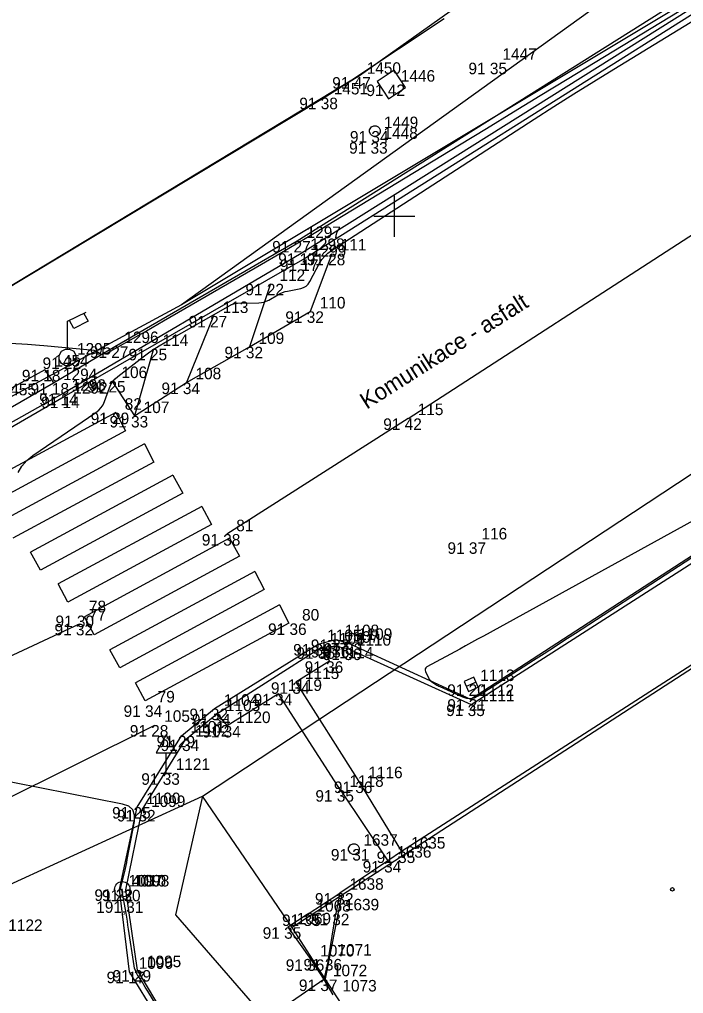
# Model space of a CAD drawing. Extents: x -711081 to -709338, y -1025122 to -1024092.
# Drawn here: x -710959.11 to -710942.97, y -1025043.88 to -1025020.22 of the extents above; entities that cross this region are included whole.
import ezdxf

# ---------------------------------------------------------------- set-up
doc = ezdxf.new("R2010")
doc.units = 0
for name, color, linetype in [('Ex_Minor Contours', 7, 'Continuous'), ('Z_bodove_pole', 7, 'Continuous'), ('Z_bodove_pole_cisla', 7, 'Continuous'), ('Z_bodove_pole_vysky', 7, 'Continuous'), ('Z_body', 7, 'Continuous'), ('Z_body_cisla', 7, 'Continuous'), ('Z_body_vysky_redukovane', 7, 'Continuous'), ('Z_budova', 7, 'Continuous'), ('Z_dopravni_znacky', 7, 'Continuous'), ('Z_hektometricka_sit', 7, 'Continuous'), ('Z_katastr_hranice', 7, 'Continuous'), ('Z_katastr_vnitrni_kresba', 7, 'Continuous'), ('Z_katastr_znacky_budov', 7, 'Continuous'), ('Z_komunikace', 7, 'Continuous'), ('Z_komunikace_osa', 7, 'Continuous'), ('Z_obruba', 7, 'Continuous'), ('Z_popisy', 7, 'Continuous'), ('Z_rozhranni', 7, 'Continuous'), ('Z_site_kanalizace_znaky', 7, 'Continuous'), ('Z_site_nerozlisene_znaky', 7, 'Continuous'), ('Z_site_vo_znaky', 7, 'Continuous'), ('Z_site_vodovod_znaky', 7, 'Continuous'), ('Z_vdz12_plna', 7, 'Continuous'), ('Z_vdz25_prerusovana', 7, 'Continuous'), ('Z_vdz50', 7, 'Continuous'), ('Z_vdz_prechod', 7, 'Continuous'), ('Z_vstupy', 7, 'Continuous')]:
    doc.layers.add(name, color=color, linetype=linetype)

# ---------------------------------------------------------------- blocks, each defined once
blk = doc.blocks.new('POINT_DISPLAY')
blk.add_line((0, 0), (0, 0))
blk = doc.blocks.new('Z614')
for p, q in [((-0.13, 0.03), (-0.1, 0.08)), ((-0.13, -0.03), (-0.13, 0.03)), ((-0.1, 0.08), (-0.08, 0.1)), ((-0.08, 0.1), (-0.03, 0.13)), ((-0.03, 0.13), (0.03, 0.13)), ((0.03, 0.13), (0.08, 0.1)), ((0.08, 0.1), (0.1, 0.08)), ((0.1, 0.08), (0.13, 0.03)), ((0.13, 0.03), (0.13, -0.03)), ((-0.1, -0.08), (-0.13, -0.03)), ((-0.08, -0.1), (-0.1, -0.08)), ((-0.03, -0.13), (-0.08, -0.1)), ((0.03, -0.13), (-0.03, -0.13)), ((0.08, -0.1), (0.03, -0.13)), ((0.1, -0.08), (0.08, -0.1)), ((0.13, -0.03), (0.1, -0.08))]:
    blk.add_line(p, q)
blk = doc.blocks.new('Z13')
for p, q in [((0, 0.88), (0.45, 1.1)), ((0.4, 1.07), (0.5, 0.88)), ((0, 0.2), (0, 0.88)), ((0.15, 0.7), (0.05, 0.9)), ((0.5, 0.88), (0.15, 0.7)), ((-0.2, 0.05), (-0.15, 0.15)), ((-0.2, -0.05), (-0.2, 0.05)), ((-0.15, 0.15), (-0.05, 0.2)), ((-0.05, 0.2), (0.05, 0.2)), ((0.05, 0.2), (0.15, 0.15)), ((0.15, 0.15), (0.2, 0.05)), ((0.2, 0.05), (0.2, -0.05)), ((-0.15, -0.15), (-0.2, -0.05)), ((-0.05, -0.2), (-0.15, -0.15)), ((0.05, -0.2), (-0.05, -0.2)), ((0.15, -0.15), (0.05, -0.2)), ((0.2, -0.05), (0.15, -0.15))]:
    blk.add_line(p, q)
blk = doc.blocks.new('Z46260')
for p, q in [((0.13, 0.13), (-0.13, 0.13)), ((-0.13, 0.13), (-0.13, -0.13)), ((0.13, 0), (-0.13, 0)), ((0.13, -0.13), (0.13, 0.13)), ((-0.13, -0.13), (0.13, -0.13))]:
    blk.add_line(p, q)
blk = doc.blocks.new('Z608')
for p, q in [((0.25, 0.25), (-0.25, 0.25)), ((-0.25, 0.25), (-0.25, -0.25)), ((0.25, -0.25), (0.25, 0.25)), ((-0.25, -0.25), (0.25, -0.25))]:
    blk.add_line(p, q)
blk = doc.blocks.new('Z527')
for p, q in [((0, 0.93), (-0.25, 0.5)), ((0.25, 0.5), (0, 0.93)), ((-0.25, 0.5), (0.25, 0.5)), ((0, 0), (0, 0.5)), ((-0.13, 0), (0.13, 0))]:
    blk.add_line(p, q)
blk = doc.blocks.new('Z101')
for radius in [0.188, 0.0025]:
    blk.add_circle((0, 0), radius)

msp = doc.modelspace()

# ---------------------------------------------------------------- linework, layer by layer
at = {"layer": 'Ex_Minor Contours'}
for points in [[(-710942.171, -1025019.465), (-710945.798, -1025021.678), (-710946.452, -1025022.076), (-710947.105, -1025022.475), (-710947.759, -1025022.873), (-710948.413, -1025023.271), (-710951.466, -1025025.128), (-710951.904, -1025025.393), (-710952.343, -1025025.655), (-710952.784, -1025025.915), (-710953.226, -1025026.172), (-710955.609, -1025027.549), (-710955.747, -1025027.628), (-710955.884, -1025027.708), (-710956.022, -1025027.787), (-710956.16, -1025027.865), (-710956.957, -1025028.32), (-710956.972, -1025028.328), (-710956.988, -1025028.334), (-710957.004, -1025028.339), (-710957.02, -1025028.342), (-710957.088, -1025028.353), (-710957.104, -1025028.354), (-710957.12, -1025028.352), (-710957.135, -1025028.347), (-710957.149, -1025028.338), (-710957.218, -1025028.29), (-710957.234, -1025028.28), (-710957.252, -1025028.273), (-710957.27, -1025028.267), (-710957.289, -1025028.264), (-710958.519, -1025028.149), (-710958.618, -1025028.14), (-710958.717, -1025028.132), (-710958.816, -1025028.124), (-710958.915, -1025028.118), (-710959.33, -1025028.091)], [(-710959.142, -1025031.227), (-710959.049, -1025031.069), (-710958.929, -1025030.93), (-710958.782, -1025030.811), (-710957.25, -1025029.766), (-710957.182, -1025029.712), (-710957.125, -1025029.649), (-710957.078, -1025029.579), (-710957.042, -1025029.5), (-710956.921, -1025029.167), (-710956.885, -1025029.087), (-710956.84, -1025029.015), (-710956.785, -1025028.949), (-710956.72, -1025028.892), (-710956.103, -1025028.415), (-710955.975, -1025028.32), (-710955.844, -1025028.229), (-710955.71, -1025028.144), (-710955.572, -1025028.063), (-710953.983, -1025027.161), (-710953.969, -1025027.154), (-710953.955, -1025027.147), (-710953.941, -1025027.142), (-710953.927, -1025027.137), (-710953.867, -1025027.118), (-710953.853, -1025027.113), (-710953.838, -1025027.11), (-710953.822, -1025027.108), (-710953.807, -1025027.108), (-710953.291, -1025027.101), (-710953.228, -1025027.096), (-710953.167, -1025027.083), (-710953.109, -1025027.063), (-710953.052, -1025027.035), (-710952.83, -1025026.905), (-710952.774, -1025026.876), (-710952.715, -1025026.851), (-710952.655, -1025026.831), (-710952.593, -1025026.816), (-710952.273, -1025026.752), (-710952.203, -1025026.73), (-710952.143, -1025026.696), (-710952.093, -1025026.649), (-710952.053, -1025026.588), (-710951.814, -1025026.142), (-710951.757, -1025026.05), (-710951.691, -1025025.967), (-710951.614, -1025025.893), (-710951.527, -1025025.829), (-710946.599, -1025022.642), (-710946.119, -1025022.334), (-710945.636, -1025022.028), (-710945.152, -1025021.725), (-710944.666, -1025021.426), (-710941.831, -1025019.69)], [(-710942.168, -1025032.08), (-710947.833, -1025035.197), (-710947.977, -1025035.276), (-710948.121, -1025035.355), (-710948.266, -1025035.434), (-710948.41, -1025035.513), (-710949.205, -1025035.947), (-710949.234, -1025035.968), (-710949.25, -1025035.994), (-710949.252, -1025036.024), (-710949.241, -1025036.058), (-710949.161, -1025036.225), (-710949.148, -1025036.25), (-710949.131, -1025036.272), (-710949.111, -1025036.291), (-710949.089, -1025036.308), (-710948.993, -1025036.371), (-710948.968, -1025036.386), (-710948.944, -1025036.4), (-710948.918, -1025036.413), (-710948.893, -1025036.426), (-710948.344, -1025036.676), (-710948.245, -1025036.708), (-710948.148, -1025036.715), (-710948.053, -1025036.695), (-710947.959, -1025036.648), (-710946.615, -1025035.785), (-710946.36, -1025035.621), (-710946.105, -1025035.457), (-710945.851, -1025035.292), (-710945.597, -1025035.127), (-710940.917, -1025032.081)], [(-710955.493, -1025044.634), (-710955.99, -1025043.822), (-710956.021, -1025043.772), (-710956.052, -1025043.722), (-710956.083, -1025043.672), (-710956.114, -1025043.622), (-710956.24, -1025043.423), (-710956.269, -1025043.372), (-710956.292, -1025043.319), (-710956.309, -1025043.264), (-710956.321, -1025043.207), (-710956.456, -1025042.319), (-710956.471, -1025042.222), (-710956.486, -1025042.126), (-710956.502, -1025042.029), (-710956.519, -1025041.932), (-710956.618, -1025041.363), (-710956.62, -1025041.359), (-710956.622, -1025041.356), (-710956.625, -1025041.354), (-710956.629, -1025041.353), (-710956.648, -1025041.351), (-710956.651, -1025041.35), (-710956.654, -1025041.348), (-710956.655, -1025041.345), (-710956.654, -1025041.341), (-710956.55, -1025040.916), (-710956.533, -1025040.843), (-710956.517, -1025040.771), (-710956.502, -1025040.698), (-710956.488, -1025040.625), (-710956.316, -1025039.705), (-710956.309, -1025039.545), (-710956.355, -1025039.421), (-710956.454, -1025039.333), (-710956.605, -1025039.281), (-710959.896, -1025038.636)]]:
    msp.add_lwpolyline(points, dxfattribs=at)
at = {"layer": 'Z_budova'}
for p, q in [((-710950.9, -1025021.62), (-710951.7, -1025022.12)), ((-710951.7, -1025022.12), (-710960.53, -1025027.43)), ((-710939.85, -1025034.02), (-710949.82, -1025040.43)), ((-710949.82, -1025040.43), (-710950.16, -1025040.66)), ((-710950.16, -1025040.66), (-710951.32, -1025041.44)), ((-710951.32, -1025041.44), (-710951.42, -1025041.94)), ((-710951.6, -1025043.04), (-710951.71, -1025043.54)), ((-710951.71, -1025043.54), (-710951.49, -1025043.91))]:
    msp.add_line(p, q, dxfattribs=at)
at = {"layer": 'Z_hektometricka_sit'}
for p, q in [((-710950, -1025024.5), (-710950, -1025025.5)), ((-710950.5, -1025025), (-710949.5, -1025025))]:
    msp.add_line(p, q, dxfattribs=at)
at = {"layer": 'Z_katastr_hranice'}
for p, q in [((-710932.67, -1025010.97), (-710955.17, -1025027.15)), ((-710942.53, -1025019.56), (-710955.17, -1025027.15)), ((-710951.03, -1025021.69), (-710948.79, -1025020.2)), ((-710964.14, -1025029.59), (-710951.03, -1025021.69)), ((-710954.66, -1025039.09), (-710931.09, -1025023.55)), ((-710955.17, -1025027.15), (-710963.45, -1025031.62)), ((-710941.71, -1025035.3), (-710951.28, -1025041.5)), ((-710988.36, -1025054.5), (-710954.66, -1025039.09)), ((-710952.48, -1025042.28), (-710954.66, -1025039.09)), ((-710951.28, -1025041.5), (-710952.48, -1025042.28)), ((-710951.68, -1025043.52), (-710952.48, -1025042.28)), ((-710949.28, -1025047.22), (-710951.68, -1025043.52))]:
    msp.add_line(p, q, dxfattribs=at)
at = {"layer": 'Z_katastr_vnitrni_kresba'}
for p, q in [((-710954.66, -1025039.09), (-710955.32, -1025041.97)), ((-710951.28, -1025041.5), (-710951.68, -1025043.52)), ((-710955.32, -1025041.97), (-710948.24, -1025050.1))]:
    msp.add_line(p, q, dxfattribs=at)
at = {"layer": 'Z_katastr_znacky_budov'}
msp.add_circle((-710943.242, -1025041.35), 0.0437, dxfattribs=at)
at = {"layer": 'Z_komunikace'}
for p, q in [((-710952.26, -1025025.9), (-710941.85, -1025019.35)), ((-710958.07, -1025029.31), (-710952.26, -1025025.9)), ((-710961.03, -1025030.98), (-710958.07, -1025029.31)), ((-710948.15, -1025036.73), (-710940.54, -1025031.79)), ((-710951.85, -1025035.39), (-710951.42, -1025035.28)), ((-710951.42, -1025035.28), (-710951.11, -1025035.37)), ((-710951.11, -1025035.37), (-710948.15, -1025036.73)), ((-710954.37, -1025036.96), (-710951.85, -1025035.39)), ((-710955.17, -1025037.62), (-710954.37, -1025036.96)), ((-710956.25, -1025039.35), (-710955.17, -1025037.62)), ((-710956.68, -1025041.35), (-710956.25, -1025039.35)), ((-710956.43, -1025043.35), (-710956.68, -1025041.35)), ((-710955.58, -1025044.75), (-710956.43, -1025043.35))]:
    msp.add_line(p, q, dxfattribs=at)
at = {"layer": 'Z_komunikace_osa'}
for q in [(-710940.68, -1025024.1), (-710954.07, -1025032.72)]:
    msp.add_line((-710949.66, -1025029.91), q, dxfattribs=at)
at = {"layer": 'Z_obruba'}
for p, q in [((-710952.36, -1025025.6), (-710941.97, -1025019.06)), ((-710956.79, -1025028.16), (-710952.36, -1025025.6)), ((-710958.28, -1025029.05), (-710956.79, -1025028.16)), ((-710961.25, -1025030.75), (-710958.28, -1025029.05)), ((-710948.13, -1025036.86), (-710940.48, -1025031.96)), ((-710954.31, -1025037.09), (-710951.77, -1025035.47)), ((-710951.77, -1025035.47), (-710951.42, -1025035.44)), ((-710951.42, -1025035.44), (-710951.13, -1025035.5)), ((-710951.13, -1025035.5), (-710948.13, -1025036.86)), ((-710955.07, -1025037.71), (-710954.31, -1025037.09)), ((-710956.13, -1025039.42), (-710955.07, -1025037.71)), ((-710956.52, -1025041.36), (-710956.13, -1025039.42)), ((-710956.24, -1025043.31), (-710956.52, -1025041.36)), ((-710955.43, -1025044.66), (-710956.24, -1025043.31))]:
    msp.add_line(p, q, dxfattribs=at)
at = {"layer": 'Z_rozhranni'}
for p, q in [((-710952.22, -1025026.05), (-710941.72, -1025019.43)), ((-710958.02, -1025029.38), (-710952.22, -1025026.05)), ((-710958.49, -1025028.73), (-710959.76, -1025029.42)), ((-710958.49, -1025028.73), (-710958.28, -1025029.05)), ((-710960.92, -1025031.05), (-710958.02, -1025029.38)), ((-710951.77, -1025035.47), (-710951.57, -1025035.81)), ((-710951.57, -1025035.81), (-710952.39, -1025036.32)), ((-710952.39, -1025036.32), (-710950.86, -1025038.73)), ((-710952.81, -1025036.6), (-710954.06, -1025037.38)), ((-710951.31, -1025038.94), (-710952.81, -1025036.6)), ((-710954.31, -1025037.09), (-710954.06, -1025037.38)), ((-710950.86, -1025038.73), (-710949.82, -1025040.43)), ((-710951.31, -1025038.94), (-710950.16, -1025040.66)), ((-710952.12, -1025041.96), (-710951.32, -1025041.44)), ((-710952.12, -1025041.96), (-710952.59, -1025042.27)), ((-710952.59, -1025042.27), (-710952.03, -1025043.05)), ((-710952.03, -1025043.05), (-710951.71, -1025043.54)), ((-710951.71, -1025043.54), (-710952.94, -1025044.39))]:
    msp.add_line(p, q, dxfattribs=at)
at = {"layer": 'Z_vdz12_plna'}
for p, q in [((-710953.52, -1025028.17), (-710952.04, -1025027.31)), ((-710955.05, -1025029.04), (-710953.52, -1025028.17)), ((-710956.86, -1025029), (-710956.31, -1025029.85)), ((-710956.31, -1025029.85), (-710955.05, -1025029.04)), ((-710959.91, -1025035.95), (-710957.65, -1025034.9))]:
    msp.add_line(p, q, dxfattribs=at)
at = {"layer": 'Z_vdz25_prerusovana'}
msp.add_line((-710960.75, -1025039.81), (-710955.82, -1025037.36), dxfattribs=at)
at = {"layer": 'Z_vdz50'}
for p, q in [((-710951.52, -1025025.91), (-710952.04, -1025027.31)), ((-710953.01, -1025026.64), (-710953.52, -1025028.17)), ((-710954.39, -1025027.42), (-710955.05, -1025029.04)), ((-710955.85, -1025028.22), (-710956.31, -1025029.85))]:
    msp.add_line(p, q, dxfattribs=at)
at = {"layer": 'Z_vdz_prechod'}
for p, q in [((-710956.77, -1025029.77), (-710960.27, -1025031.66)), ((-710956.77, -1025029.77), (-710956.53, -1025030.21)), ((-710956.53, -1025030.21), (-710960.03, -1025032.1)), ((-710956.07, -1025030.53), (-710959.5, -1025032.38)), ((-710956.07, -1025030.53), (-710955.84, -1025030.97)), ((-710955.84, -1025030.97), (-710959.27, -1025032.82)), ((-710955.38, -1025031.29), (-710958.84, -1025033.16)), ((-710955.38, -1025031.29), (-710955.14, -1025031.73)), ((-710955.14, -1025031.73), (-710958.6, -1025033.6)), ((-710954.68, -1025032.05), (-710958.17, -1025033.93)), ((-710954.68, -1025032.05), (-710954.44, -1025032.49)), ((-710954.44, -1025032.49), (-710957.93, -1025034.37)), ((-710954, -1025032.82), (-710957.53, -1025034.73)), ((-710954, -1025032.82), (-710953.76, -1025033.26)), ((-710958.6, -1025033.6), (-710958.84, -1025033.16)), ((-710953.76, -1025033.26), (-710957.29, -1025035.17)), ((-710953.39, -1025033.63), (-710956.91, -1025035.53)), ((-710953.39, -1025033.63), (-710953.16, -1025034.07)), ((-710957.93, -1025034.37), (-710958.17, -1025033.93)), ((-710953.16, -1025034.07), (-710956.67, -1025035.97)), ((-710952.79, -1025034.44), (-710956.29, -1025036.33)), ((-710952.79, -1025034.44), (-710952.56, -1025034.88)), ((-710957.29, -1025035.17), (-710957.53, -1025034.73)), ((-710952.56, -1025034.88), (-710956.05, -1025036.77)), ((-710956.67, -1025035.97), (-710956.91, -1025035.53)), ((-710956.05, -1025036.77), (-710956.29, -1025036.33))]:
    msp.add_line(p, q, dxfattribs=at)
at = {"layer": 'Z_vstupy'}
for p, q in [((-710950.9, -1025021.62), (-710948.33, -1025019.8)), ((-710951.6, -1025043.04), (-710951.42, -1025041.94))]:
    msp.add_line(p, q, dxfattribs=at)

# ---------------------------------------------------------------- block references
at = {"layer": 'Z_bodove_pole'}
msp.add_blockref('Z101', (-710956.61, -1025041.35), dxfattribs=at)
at = {"layer": 'Z_body'}
for p in [(-710947.59, -1025021.27), (-710950.9, -1025021.62), (-710950.07, -1025021.8), (-710951.7, -1025022.12), (-710950.47, -1025022.93), (-710950.49, -1025023.2), (-710952.36, -1025025.6), (-710952.26, -1025025.9), (-710951.52, -1025025.91), (-710952.22, -1025026.05), (-710953.01, -1025026.64), (-710952.04, -1025027.31), (-710954.39, -1025027.42), (-710956.79, -1025028.16), (-710955.85, -1025028.22), (-710953.52, -1025028.17), (-710957.94, -1025028.43), (-710958.49, -1025028.73), (-710958.28, -1025029.05), (-710956.86, -1025029), (-710955.05, -1025029.04), (-710958.07, -1025029.31), (-710958.02, -1025029.38), (-710956.77, -1025029.77), (-710956.31, -1025029.85), (-710949.66, -1025029.91), (-710954.07, -1025032.72), (-710948.1, -1025032.92), (-710957.65, -1025034.7), (-710957.65, -1025034.9), (-710952.46, -1025034.89), (-710951.42, -1025035.28), (-710951.11, -1025035.37), (-710951.85, -1025035.39), (-710951.77, -1025035.47), (-710951.42, -1025035.44), (-710951.13, -1025035.5), (-710951.57, -1025035.81), (-710952.39, -1025036.32), (-710948.13, -1025036.37), (-710952.81, -1025036.6), (-710948.15, -1025036.73), (-710955.97, -1025036.88), (-710954.37, -1025036.96), (-710948.13, -1025036.86), (-710954.31, -1025037.09), (-710955.82, -1025037.36), (-710954.06, -1025037.38), (-710955.17, -1025037.62), (-710955.07, -1025037.71), (-710955.54, -1025038.53), (-710950.86, -1025038.73), (-710951.31, -1025038.94), (-710956.25, -1025039.35), (-710956.13, -1025039.42), (-710950.98, -1025040.37), (-710949.82, -1025040.43), (-710950.16, -1025040.66), (-710956.68, -1025041.35), (-710956.61, -1025041.35), (-710956.52, -1025041.36), (-710951.32, -1025041.44), (-710952.12, -1025041.96), (-710951.42, -1025041.94), (-710952.59, -1025042.27), (-710952.03, -1025043.05), (-710951.6, -1025043.04), (-710956.43, -1025043.35), (-710956.24, -1025043.31), (-710951.71, -1025043.54)]:
    msp.add_blockref('POINT_DISPLAY', p, dxfattribs=at)
at = {"layer": 'Z_dopravni_znacky'}
msp.add_blockref('Z527', (-710955.54, -1025038.53), dxfattribs=at)
at = {"layer": 'Z_site_kanalizace_znaky', "rotation": 23.399999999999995}
msp.add_blockref('Z46260', (-710948.13, -1025036.37), dxfattribs=at)
at = {"layer": 'Z_site_nerozlisene_znaky', "rotation": 33.3}
msp.add_blockref('Z608', (-710950.07, -1025021.8), dxfattribs=at)
at = {"layer": 'Z_site_vo_znaky'}
msp.add_blockref('Z13', (-710957.94, -1025028.43), dxfattribs=at)
at = {"layer": 'Z_site_vodovod_znaky'}
for p in [(-710950.47, -1025022.93), (-710950.98, -1025040.37)]:
    msp.add_blockref('Z614', p, dxfattribs=at)

# ---------------------------------------------------------------- texts
at = {"layer": 'Z_bodove_pole_cisla'}
msp.add_text('4010', height=0.28, dxfattribs=at).set_placement((-710956.38, -1025041.28))
at = {"layer": 'Z_bodove_pole_vysky'}
msp.add_text('191,31', height=0.28, dxfattribs=at).set_placement((-710957.243, -1025041.92))
at = {"layer": 'Z_body_cisla'}
for s, p in [('1447', (-710947.37, -1025021.2)), ('1450', (-710950.67, -1025021.54)), ('1446', (-710949.84, -1025021.73)), ('1451', (-710951.47, -1025022.04)), ('1449', (-710950.25, -1025022.86)), ('1448', (-710950.26, -1025023.12)), ('1297', (-710952.13, -1025025.53)), ('1298', (-710952.04, -1025025.82)), ('111', (-710951.3, -1025025.83)), ('1299', (-710952, -1025025.98)), ('112', (-710952.79, -1025026.57)), ('113', (-710954.17, -1025027.35)), ('110', (-710951.81, -1025027.24)), ('1296', (-710956.56, -1025028.08)), ('114', (-710955.63, -1025028.15)), ('109', (-710953.3, -1025028.1)), ('1295', (-710957.71, -1025028.36)), ('1454', (-710958.26, -1025028.65)), ('1294', (-710958.05, -1025028.98)), ('106', (-710956.63, -1025028.93)), ('108', (-710954.83, -1025028.96)), ('1293', (-710957.84, -1025029.24)), ('1455', (-710959.54, -1025029.35)), ('1292', (-710957.8, -1025029.31)), ('82', (-710956.55, -1025029.7)), ('107', (-710956.09, -1025029.78)), ('115', (-710949.43, -1025029.83)), ('81', (-710953.84, -1025032.65)), ('116', (-710947.88, -1025032.85)), ('78', (-710957.42, -1025034.62)), ('77', (-710957.42, -1025034.82)), ('80', (-710952.24, -1025034.82)), ('1105', (-710951.63, -1025035.32)), ('1106', (-710951.55, -1025035.4)), ('1108', (-710951.2, -1025035.2)), ('1107', (-710951.2, -1025035.36)), ('1110', (-710950.91, -1025035.43)), ('1109', (-710950.88, -1025035.29)), ('1114', (-710951.34, -1025035.74)), ('1115', (-710952.17, -1025036.24)), ('1113', (-710947.91, -1025036.29)), ('1119', (-710952.59, -1025036.53)), ('79', (-710955.75, -1025036.81)), ('1112', (-710947.92, -1025036.65)), ('1111', (-710947.91, -1025036.78)), ('1104', (-710954.14, -1025036.89)), ('1103', (-710954.09, -1025037.02)), ('105', (-710955.59, -1025037.28)), ('1120', (-710953.84, -1025037.31)), ('1101', (-710954.95, -1025037.54)), ('1102', (-710954.84, -1025037.64)), ('1121', (-710955.31, -1025038.45)), ('1116', (-710950.63, -1025038.65)), ('1118', (-710951.09, -1025038.86)), ('1100', (-710956.03, -1025039.28)), ('1099', (-710955.91, -1025039.35)), ('1637', (-710950.75, -1025040.29)), ('1635', (-710949.59, -1025040.36)), ('1636', (-710949.93, -1025040.58)), ('1097', (-710956.46, -1025041.28)), ('1098', (-710956.3, -1025041.28)), ('1638', (-710951.09, -1025041.36)), ('1068', (-710951.89, -1025041.89)), ('1639', (-710951.2, -1025041.86)), ('1069', (-710952.37, -1025042.2)), ('1122', (-710959.38, -1025042.36)), ('1070', (-710951.8, -1025042.98)), ('1071', (-710951.38, -1025042.96)), ('1096', (-710956.21, -1025043.28)), ('1095', (-710956.01, -1025043.24)), ('1072', (-710951.49, -1025043.46)), ('1073', (-710951.26, -1025043.83))]:
    msp.add_text(s, height=0.28, dxfattribs=at).set_placement(p)
at = {"layer": 'Z_body_vysky_redukovane'}
for s, p in [('91 35', (-710948.197, -1025021.55)), ('91 47', (-710951.507, -1025021.9)), ('91 42', (-710950.677, -1025022.08)), ('91 38', (-710952.307, -1025022.4)), ('91 34', (-710951.077, -1025023.21)), ('91 33', (-710951.097, -1025023.48)), ('91 27', (-710952.967, -1025025.88)), ('91 17', (-710952.82, -1025026.18)), ('91 28', (-710952.127, -1025026.19)), ('91 17', (-710952.78, -1025026.33)), ('91 22', (-710953.617, -1025026.92)), ('91 32', (-710952.647, -1025027.59)), ('91 27', (-710954.997, -1025027.7)), ('91 27', (-710957.397, -1025028.44)), ('91 25', (-710956.457, -1025028.5)), ('91 32', (-710954.127, -1025028.45)), ('91 22', (-710958.547, -1025028.71)), ('91 18', (-710959.05, -1025029.01)), ('91 18', (-710958.84, -1025029.33)), ('91 25', (-710957.467, -1025029.28)), ('91 34', (-710955.657, -1025029.32)), ('91 14', (-710958.63, -1025029.59)), ('91 14', (-710958.58, -1025029.66)), ('91 29', (-710957.377, -1025030.05)), ('91 33', (-710956.917, -1025030.13)), ('91 42', (-710950.267, -1025030.19)), ('91 38', (-710954.677, -1025033)), ('91 37', (-710948.707, -1025033.2)), ('91 32', (-710958.257, -1025035.18)), ('91 30', (-710958.233, -1025034.98)), ('91 36', (-710953.067, -1025035.17)), ('91 33', (-710952.027, -1025035.56)), ('91 33', (-710951.717, -1025035.65)), ('91 34', (-710952.457, -1025035.67)), ('91 36', (-710952.377, -1025035.75)), ('91 36', (-710952.027, -1025035.72)), ('91 36', (-710951.737, -1025035.78)), ('91 36', (-710952.177, -1025036.09)), ('91 34', (-710952.997, -1025036.6)), ('91 20', (-710948.713, -1025036.65)), ('91 34', (-710953.417, -1025036.88)), ('91 21', (-710948.71, -1025037.01)), ('91 34', (-710956.577, -1025037.16)), ('91 32', (-710954.977, -1025037.24)), ('91 35', (-710948.737, -1025037.14)), ('91 34', (-710954.917, -1025037.37)), ('91 28', (-710956.427, -1025037.64)), ('91 34', (-710954.667, -1025037.66)), ('91 29', (-710955.777, -1025037.9)), ('91 34', (-710955.677, -1025037.99)), ('91 33', (-710956.147, -1025038.81)), ('91 36', (-710951.467, -1025039.01)), ('91 35', (-710951.917, -1025039.22)), ('91 25', (-710956.857, -1025039.63)), ('91 32', (-710956.737, -1025039.7)), ('91 31', (-710951.54, -1025040.65)), ('91 35', (-710950.427, -1025040.71)), ('91 34', (-710950.767, -1025040.94)), ('91 22', (-710957.287, -1025041.63)), ('91 30', (-710957.103, -1025041.64)), ('91 32', (-710951.927, -1025041.72)), ('91 35', (-710952.727, -1025042.24)), ('91 32', (-710952.027, -1025042.22)), ('91 35', (-710953.197, -1025042.55)), ('91 36', (-710952.637, -1025043.33)), ('91 36', (-710952.207, -1025043.32)), ('91 17', (-710956.99, -1025043.63)), ('91 29', (-710956.847, -1025043.59)), ('91 37', (-710952.317, -1025043.82))]:
    msp.add_text(s, height=0.28, dxfattribs=at).set_placement(p)
at = {"layer": 'Z_popisy'}
msp.add_text('Komunikace - asfalt', height=0.4, rotation=32.4, dxfattribs=at).set_placement((-710950.67, -1025029.7))

doc.saveas('drawing.dxf')
